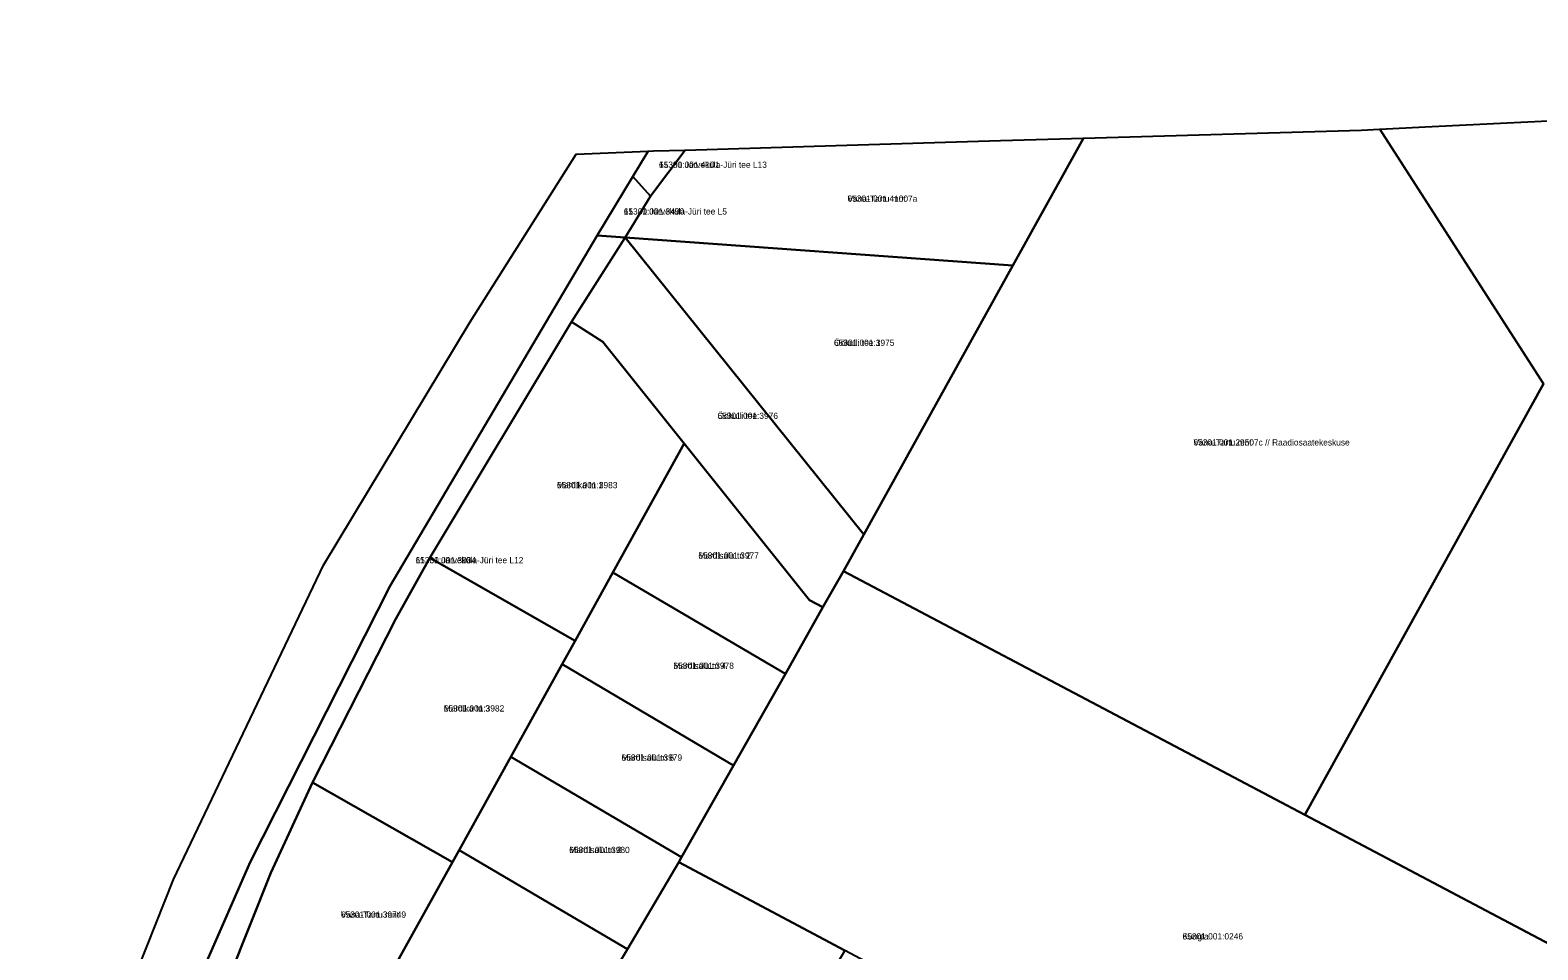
# Model space of a CAD drawing. Extents: x 543236 to 563717, y 6566033 to 6588992.
# Drawn here: x 545062.9 to 545424.5, y 6585592.9 to 6585813.4 of the extents above; entities that cross this region are included whole.
import ezdxf

# ---------------------------------------------------------------- set-up
doc = ezdxf.new("R2010")
doc.units = 0
for name, color, linetype in [('L_AADRESS', 7, 'Continuous'), ('PIIR', 7, 'Continuous'), ('TUNNUS', 7, 'Continuous')]:
    doc.layers.add(name, color=color, linetype=linetype)

msp = doc.modelspace()

# ---------------------------------------------------------------- linework, layer by layer
at = {"layer": 'PIIR'}
for points in [[(545425.81, 6585728.57), (545386.6, 6585789.64), (545397.45, 6585790.16), (545449.96, 6585792.7), (545451.89, 6585752.73), (545476.86, 6585753.94), (545474.93, 6585793.9), (545542.49, 6585797.16), (545552.36, 6585797.91), (545755.33, 6585813.35), (545739.35, 6585782.54), (545726.7, 6585758.04), (545753.02, 6585687.08), (545743.18, 6585670.16), (545721.07, 6585632.04), (545712.97, 6585618.1), (545703.85, 6585603.13), (545682.25, 6585567.64), (545641.24, 6585588.27), (545621.51, 6585548.98), (545598.51, 6585503.68), (545576.29, 6585515.4), (545456.92, 6585578.61), (545368.54, 6585625.24)], [(545298.54, 6585756.96), (545315.47, 6585787.46), (545382.09, 6585789.4), (545386.6, 6585789.64), (545425.81, 6585728.57), (545368.54, 6585625.24), (545257.92, 6585683.69), (545262.77, 6585692.44)], [(545211.63, 6585773.54), (545219.93, 6585784.62), (545256.07, 6585785.71), (545295.57, 6585786.87), (545315.47, 6585787.46), (545298.54, 6585756.96), (545205.59, 6585763.61)], [(545207.42, 6585778.3), (545211.1, 6585784.35), (545212.39, 6585784.39), (545219.93, 6585784.62), (545211.63, 6585773.54)], [(545198.81, 6585764.09), (545207.42, 6585778.3), (545211.63, 6585773.54), (545205.59, 6585763.61)], [(545149.24, 6585680.14), (545198.81, 6585764.09), (545205.59, 6585763.61), (545192.66, 6585743.39), (545158.71, 6585686.84), (545150.55, 6585672.23), (545130.58, 6585633), (545120.62, 6585611.32), (545110.66, 6585586.5), (545104.98, 6585589.57), (545115.61, 6585613.91)], [(545192.66, 6585743.39), (545205.59, 6585763.61), (545262.77, 6585692.44), (545257.92, 6585683.69), (545252.99, 6585674.99), (545249.75, 6585676.7), (545219.71, 6585714.26), (545200.24, 6585738.62)], [(545262.77, 6585692.44), (545205.59, 6585763.61), (545298.54, 6585756.96)], [(545158.71, 6585686.84), (545192.66, 6585743.39), (545200.24, 6585738.62), (545219.71, 6585714.26), (545202.63, 6585683.37), (545193.56, 6585666.96)], [(545202.63, 6585683.37), (545219.71, 6585714.26), (545249.75, 6585676.7), (545252.99, 6585674.99), (545243.98, 6585659.04)], [(545150.55, 6585672.23), (545158.71, 6585686.84), (545193.56, 6585666.96), (545190.45, 6585661.34), (545178.14, 6585639.14), (545165.73, 6585616.74), (545164.15, 6585613.91), (545130.58, 6585633)], [(545193.56, 6585666.96), (545202.63, 6585683.37), (545243.98, 6585659.04), (545231.57, 6585637.1), (545190.45, 6585661.34)], [(545257.92, 6585683.69), (545368.54, 6585625.24), (545456.92, 6585578.61), (545419.18, 6585507.02), (545369.63, 6585533.4), (545338.12, 6585550.18), (545308.06, 6585566.2), (545258.21, 6585592.75), (545218.46, 6585613.93), (545219.11, 6585615.08), (545231.57, 6585637.1), (545243.98, 6585659.04), (545252.99, 6585674.99)], [(545178.14, 6585639.14), (545190.45, 6585661.34), (545231.57, 6585637.1), (545219.11, 6585615.08)], [(545165.73, 6585616.74), (545178.14, 6585639.14), (545219.11, 6585615.08), (545218.46, 6585613.93), (545206.15, 6585593)], [(545120.62, 6585611.32), (545130.58, 6585633), (545164.15, 6585613.91), (545140.13, 6585570.54), (545118.1, 6585582.47), (545110.66, 6585586.5)], [(545140.13, 6585570.54), (545164.15, 6585613.91), (545165.73, 6585616.74), (545206.15, 6585593), (545201.04, 6585584.55), (545193.56, 6585571.71), (545182.04, 6585552.05), (545180.18, 6585548.84), (545165.35, 6585556.85)], [(545218.46, 6585613.93), (545258.21, 6585592.75), (545243.05, 6585566.97), (545232.7, 6585573.05), (545229.6, 6585567.81), (545201.04, 6585584.55), (545206.15, 6585593)]]:
    msp.add_lwpolyline(points, close=True, dxfattribs=at)
msp.add_lwpolyline([(545062.86, 6585523.19), (545097.2, 6585609.71), (545133.18, 6585685.11), (545168.38, 6585743.46), (545193.84, 6585783.66), (545211.1, 6585784.35), (545207.42, 6585778.3), (545198.81, 6585764.09), (545149.24, 6585680.14), (545115.61, 6585613.91), (545104.98, 6585589.57)], dxfattribs=at)

# ---------------------------------------------------------------- texts
at = {"layer": 'L_AADRESS'}
for s, p in [('11330 Järveküla-Jüri tee L13', (545213.68, 6585780.35)), ('Vana-Tartu mnt 7a', (545258.91, 6585772.21)), ('11330 Järveküla-Jüri tee L5', (545205.22, 6585769.15)), ('Öökulli tee 1', (545255.63, 6585737.67)), ('Öökulli tee', (545227.71, 6585720.16)), ('Vana-Tartu mnt 7c // Raadiosaatekeskuse', (545341.87, 6585713.78)), ('Mardika tn 1', (545189.21, 6585703.54)), ('11330 Järveküla-Jüri tee L12', (545155.29, 6585685.54)), ('Mardisalu tn 2', (545223.12, 6585686.65)), ('Mardisalu tn 4', (545217.14, 6585660.24)), ('Mardika tn 3', (545162.07, 6585650.01)), ('Mardisalu tn 6', (545204.71, 6585638.21)), ('Mardisalu tn 8', (545192.15, 6585616.07)), ('Vana-Tartu mnt 9', (545137.4, 6585600.57)), ('Kungla', (545339.25, 6585595.36))]:
    msp.add_text(s, height=1.5, dxfattribs=at).set_placement(p)
at = {"layer": 'TUNNUS'}
for s, p in [('65301:001:4101', (545213.68, 6585780.35)), ('65301:001:4100', (545258.91, 6585772.21)), ('65301:001:3490', (545205.22, 6585769.15)), ('65301:001:3975', (545255.63, 6585737.67)), ('65301:001:3976', (545227.71, 6585720.16)), ('65301:001:2950', (545341.87, 6585713.78)), ('65301:001:3983', (545189.21, 6585703.54)), ('65301:001:3984', (545155.29, 6585685.54)), ('65301:001:3977', (545223.12, 6585686.65)), ('65301:001:3978', (545217.14, 6585660.24)), ('65301:001:3982', (545162.07, 6585650.01)), ('65301:001:3979', (545204.71, 6585638.21)), ('65301:001:3980', (545192.15, 6585616.07)), ('65301:001:3974', (545137.4, 6585600.57)), ('65301:001:0246', (545339.25, 6585595.36))]:
    msp.add_text(s, height=1.5, dxfattribs=at).set_placement(p)

doc.saveas('drawing.dxf')
